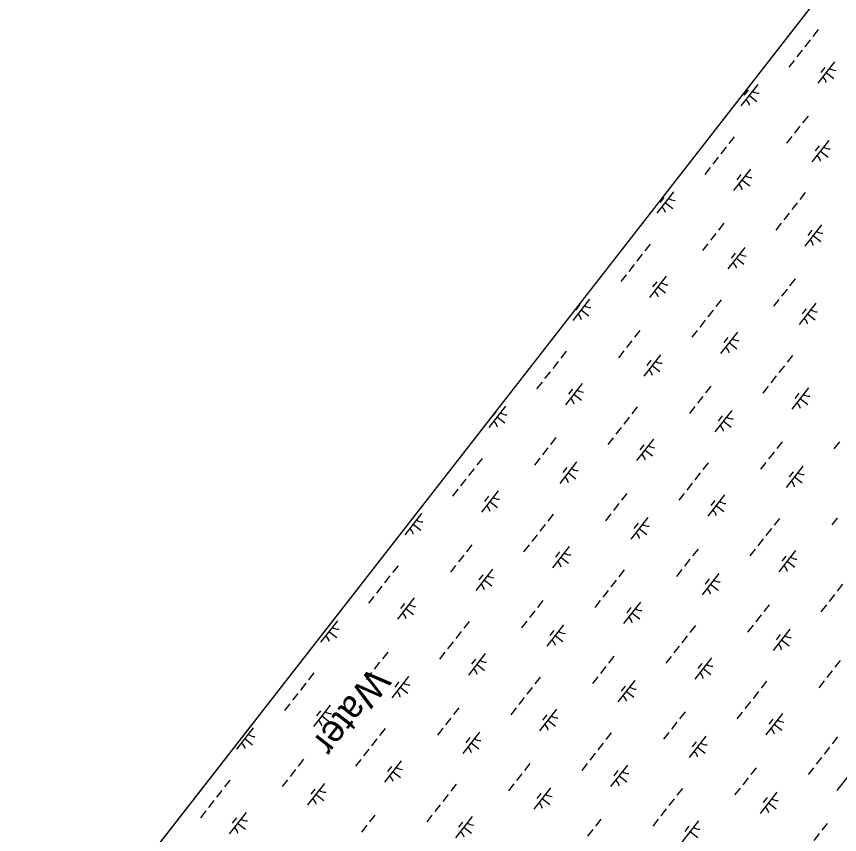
# Model space of a CAD drawing. Extents: x 3896831 to 3918110, y 171006 to 193349.
# Drawn here: x 3901021 to 3902537, y 179403 to 180910 of the extents above; entities that cross this region are included whole.
import ezdxf

# ---------------------------------------------------------------- set-up
doc = ezdxf.new("R2010")
doc.units = 0
for name, color, linetype in [('V-GRID-FRAM', 7, 'Continuous'), ('V-RIVR-IDEN', 7, 'Continuous'), ('V-WETL-SWMP', 7, 'Continuous')]:
    doc.layers.add(name, color=color, linetype=linetype)

msp = doc.modelspace()

# ---------------------------------------------------------------- linework, layer by layer
at = {"layer": 'V-GRID-FRAM'}
msp.add_lwpolyline([(3916044.9, 184610), (3906752.8, 172754.1), (3900055.1, 177809.8), (3909313.3, 189695.8), (3916044.9, 184610)], dxfattribs=at)
at = {"layer": 'V-WETL-SWMP'}
for p, q in [((3902531.9, 180989.7), (3901227.8, 179315.5)), ((3902497.5, 180886.2), (3902487.7, 180873.6)), ((3902482.7, 180867.3), (3902472.9, 180854.7)), ((3902467.9, 180848.4), (3902458.1, 180835.8)), ((3902453.1, 180829.5), (3902443.3, 180816.9)), ((3902527.3, 180826.8), (3902496.4, 180787.4)), ((3902509.5, 180816.6), (3902502.1, 180807.1)), ((3902511.8, 180807.1), (3902526, 180796)), ((3902385.9, 180784.8), (3902355, 180745.5)), ((3902368.1, 180774.6), (3902360.7, 180765.2)), ((3902370.4, 180765.2), (3902384.6, 180754)), ((3902478.6, 180727), (3902468.7, 180714.4)), ((3902463.8, 180708.1), (3902453.9, 180695.6)), ((3902342.7, 180688.7), (3902332.9, 180676.1)), ((3902449, 180689.3), (3902439.1, 180676.7)), ((3902516.8, 180682.2), (3902485.9, 180642.9)), ((3902499, 180672), (3902491.6, 180662.6)), ((3902327.9, 180669.8), (3902318.1, 180657.2)), ((3902501.4, 180662.5), (3902515.5, 180651.4)), ((3902313.1, 180650.9), (3902303.3, 180638.3)), ((3902298.3, 180632), (3902288.4, 180619.4)), ((3902372.4, 180629.3), (3902341.6, 180589.9)), ((3902354.7, 180619.1), (3902347.3, 180609.6)), ((3902357, 180609.6), (3902371.2, 180598.5)), ((3902231.1, 180587.3), (3902200.2, 180548)), ((3902473.6, 180586.1), (3902463.8, 180573.5)), ((3902213.3, 180577.1), (3902205.9, 180567.7)), ((3902215.6, 180567.6), (3902229.8, 180556.5)), ((3902458.8, 180567.2), (3902449, 180554.6)), ((3902444, 180548.3), (3902434.2, 180535.7)), ((3902323.8, 180529.5), (3902313.9, 180516.9)), ((3902429.2, 180529.4), (3902419.4, 180516.8)), ((3902503.4, 180526.6), (3902472.5, 180487.3)), ((3902309, 180510.6), (3902299.1, 180498)), ((3902485.6, 180516.5), (3902478.2, 180507)), ((3902487.9, 180507), (3902502.1, 180495.9)), ((3902187.9, 180491.1), (3902178.1, 180478.6)), ((3902294.2, 180491.7), (3902284.3, 180479.1)), ((3902362, 180484.7), (3902331.1, 180445.3)), ((3902344.2, 180474.5), (3902336.8, 180465.1)), ((3902173.1, 180472.3), (3902163.2, 180459.7)), ((3902346.6, 180465), (3902360.7, 180453.9)), ((3902158.3, 180453.4), (3902148.4, 180440.8)), ((3902143.5, 180434.5), (3902133.6, 180421.9)), ((3902217.6, 180431.7), (3902186.8, 180392.4)), ((3902199.9, 180421.5), (3902192.4, 180412.1)), ((3902454.7, 180426.9), (3902444.8, 180414.3)), ((3902202.2, 180412.1), (3902216.4, 180401)), ((3902439.9, 180408), (3902430, 180395.4)), ((3902076.3, 180389.8), (3902045.4, 180350.4)), ((3902318.8, 180388.5), (3902309, 180375.9)), ((3902425.1, 180389.1), (3902415.2, 180376.5)), ((3902492.9, 180382.1), (3902462.1, 180342.7)), ((3902058.5, 180379.6), (3902051.1, 180370.2)), ((3902060.8, 180370.1), (3902075, 180359)), ((3902304, 180369.6), (3902294.2, 180357.1)), ((3902475.1, 180371.9), (3902467.7, 180362.5)), ((3902477.5, 180362.4), (3902491.6, 180351.3)), ((3902289.2, 180350.8), (3902279.4, 180338.2)), ((3902169, 180332), (3902159.1, 180319.4)), ((3902274.4, 180331.9), (3902264.6, 180319.3)), ((3902348.6, 180329.1), (3902317.7, 180289.8)), ((3902154.2, 180313.1), (3902144.3, 180300.5)), ((3902330.8, 180318.9), (3902323.4, 180309.5)), ((3902333.1, 180309.5), (3902347.3, 180298.4)), ((3902033.1, 180293.6), (3902023.2, 180281)), ((3902139.4, 180294.2), (3902129.5, 180281.6)), ((3902207.2, 180287.2), (3902176.3, 180247.8)), ((3902189.4, 180277), (3902182, 180267.5)), ((3902449.8, 180285.9), (3902439.9, 180273.3)), ((3902018.3, 180274.7), (3902008.4, 180262.1)), ((3902191.8, 180267.5), (3902205.9, 180256.4)), ((3902435, 180267), (3902425.1, 180254.4)), ((3902003.5, 180255.8), (3901993.6, 180243.3)), ((3902420.2, 180248.1), (3902410.3, 180235.6)), ((3901988.7, 180237), (3901978.8, 180224.4)), ((3902062.8, 180234.2), (3902032, 180194.9)), ((3902045, 180224), (3902037.6, 180214.6)), ((3902299.9, 180229.4), (3902290, 180216.8)), ((3902405.3, 180229.3), (3902395.5, 180216.7)), ((3902479.5, 180226.5), (3902448.6, 180187.2)), ((3902461.7, 180216.3), (3902454.3, 180206.9)), ((3902047.4, 180214.5), (3902061.6, 180203.4)), ((3902285.1, 180210.5), (3902275.2, 180197.9)), ((3902464.1, 180206.8), (3902478.2, 180195.7)), ((3901921.4, 180192.3), (3901890.6, 180152.9)), ((3902164, 180191), (3902154.2, 180178.4)), ((3902270.3, 180191.6), (3902260.4, 180179)), ((3901903.7, 180182.1), (3901896.3, 180172.6)), ((3901906, 180172.6), (3901920.2, 180161.5)), ((3902149.2, 180172.1), (3902139.4, 180159.5)), ((3902338.1, 180184.6), (3902307.2, 180145.2)), ((3902320.3, 180174.4), (3902312.9, 180164.9)), ((3902322.7, 180164.9), (3902336.8, 180153.8)), ((3902134.4, 180153.2), (3902124.6, 180140.6)), ((3902014.2, 180134.5), (3902004.3, 180121.9)), ((3902119.6, 180134.4), (3902109.8, 180121.8)), ((3902193.8, 180131.6), (3902162.9, 180092.3)), ((3902430.8, 180126.8), (3902420.9, 180114.2)), ((3902536.3, 180126.7), (3902526.4, 180114.1)), ((3901999.4, 180115.6), (3901989.5, 180103)), ((3902176, 180121.4), (3902168.6, 180112)), ((3902178.3, 180111.9), (3902192.5, 180100.8)), ((3901878.3, 180096.1), (3901868.4, 180083.5)), ((3901984.5, 180096.7), (3901974.7, 180084.1)), ((3902416, 180107.9), (3902406.1, 180095.3)), ((3902052.4, 180089.7), (3902021.5, 180050.3)), ((3902034.6, 180079.5), (3902027.2, 180070)), ((3902295, 180088.4), (3902285.1, 180075.8)), ((3902401.2, 180089), (3902391.3, 180076.4)), ((3902469, 180082), (3902438.2, 180042.6)), ((3901863.5, 180077.2), (3901853.6, 180064.6)), ((3902036.9, 180070), (3902051.1, 180058.9)), ((3902280.2, 180069.5), (3902270.3, 180056.9)), ((3902451.2, 180071.8), (3902443.8, 180062.3)), ((3901848.7, 180058.3), (3901838.8, 180045.7)), ((3902265.3, 180050.6), (3902255.5, 180038)), ((3902453.6, 180062.3), (3902467.8, 180051.2)), ((3901833.9, 180039.4), (3901824, 180026.8)), ((3901908, 180036.7), (3901877.2, 179997.4)), ((3901890.2, 180026.5), (3901882.8, 180017.1)), ((3902145.1, 180031.9), (3902135.2, 180019.3)), ((3902250.5, 180031.7), (3902240.7, 180019.1)), ((3902324.7, 180029), (3902293.8, 179989.7)), ((3902306.9, 180018.8), (3902299.5, 180009.4)), ((3901892.6, 180017), (3901906.8, 180005.9)), ((3902130.3, 180013), (3902120.4, 180000.4)), ((3902309.3, 180009.3), (3902323.4, 179998.2)), ((3901766.6, 179994.8), (3901735.8, 179955.4)), ((3902009.2, 179993.5), (3901999.4, 179980.9)), ((3902115.5, 179994.1), (3902105.6, 179981.5)), ((3901751.2, 179975.1), (3901765.4, 179964)), ((3901994.4, 179974.6), (3901984.6, 179962)), ((3902183.3, 179987.1), (3902152.4, 179947.7)), ((3902165.5, 179976.9), (3902158.1, 179967.4)), ((3902425.9, 179985.8), (3902416, 179973.2)), ((3902532.1, 179986.4), (3902522.2, 179973.8)), ((3902167.9, 179967.4), (3902182, 179956.3)), ((3902411.1, 179966.9), (3902401.2, 179954.3)), ((3901979.6, 179955.7), (3901969.8, 179943.1)), ((3902396.3, 179948), (3902386.4, 179935.4)), ((3901859.4, 179937), (3901849.5, 179924.4)), ((3901964.8, 179936.8), (3901954.9, 179924.2)), ((3902039, 179934.1), (3902008.1, 179894.7)), ((3902276, 179929.3), (3902266.1, 179916.7)), ((3902381.5, 179929.1), (3902371.6, 179916.5)), ((3901844.5, 179918.1), (3901834.7, 179905.5)), ((3902021.2, 179923.9), (3902013.8, 179914.5)), ((3902023.5, 179914.4), (3902037.7, 179903.3)), ((3902455.6, 179926.4), (3902424.7, 179887)), ((3902437.8, 179916.2), (3902430.4, 179906.8)), ((3901723.5, 179898.6), (3901713.6, 179886)), ((3901829.7, 179899.2), (3901819.9, 179886.6)), ((3902261.2, 179910.4), (3902251.3, 179897.8)), ((3902440.2, 179906.7), (3902454.3, 179895.6)), ((3901897.6, 179892.1), (3901866.7, 179852.8)), ((3901879.8, 179882), (3901872.4, 179872.5)), ((3902140.1, 179890.9), (3902130.3, 179878.3)), ((3902246.4, 179891.5), (3902236.5, 179878.9)), ((3902314.2, 179884.4), (3902283.4, 179845.1)), ((3901708.7, 179879.7), (3901698.8, 179867.1)), ((3901882.1, 179872.5), (3901896.3, 179861.4)), ((3902125.3, 179872), (3902115.5, 179859.4)), ((3902296.4, 179874.3), (3902289, 179864.8)), ((3901693.9, 179860.8), (3901684, 179848.2)), ((3902110.5, 179853.1), (3902100.7, 179840.5)), ((3902298.8, 179864.8), (3902312.9, 179853.7)), ((3902542, 179864.3), (3902532.1, 179851.7)), ((3901679.1, 179841.9), (3901669.2, 179829.3)), ((3901753.2, 179839.2), (3901722.4, 179799.8)), ((3902527.2, 179845.4), (3902517.3, 179832.8)), ((3901735.4, 179829), (3901728, 179819.6)), ((3901990.3, 179834.4), (3901980.4, 179821.8)), ((3902095.7, 179834.2), (3902085.9, 179821.6)), ((3902169.9, 179831.5), (3902139, 179792.1)), ((3902152.1, 179821.3), (3902144.7, 179811.9)), ((3902406.9, 179826.7), (3902397, 179814.1)), ((3902512.4, 179826.5), (3902502.5, 179813.9)), ((3901737.8, 179819.5), (3901752, 179808.4)), ((3901975.5, 179815.5), (3901965.6, 179802.9)), ((3902154.4, 179811.8), (3902168.6, 179800.7)), ((3902392.1, 179807.8), (3902382.2, 179795.2)), ((3901611.8, 179797.2), (3901581, 179757.9)), ((3901854.4, 179796), (3901844.6, 179783.4)), ((3901960.7, 179796.6), (3901950.8, 179784)), ((3901596.4, 179777.6), (3901610.6, 179766.5)), ((3901839.6, 179777.1), (3901829.8, 179764.5)), ((3902028.5, 179789.5), (3901997.6, 179750.2)), ((3902010.7, 179779.3), (3902003.3, 179769.9)), ((3902271.1, 179788.3), (3902261.2, 179775.7)), ((3902377.3, 179788.9), (3902367.4, 179776.3)), ((3902445.1, 179781.8), (3902414.3, 179742.5)), ((3902013.1, 179769.9), (3902027.2, 179758.8)), ((3902256.3, 179769.4), (3902246.4, 179756.8)), ((3902427.3, 179771.6), (3902419.9, 179762.2)), ((3902429.7, 179762.2), (3902443.9, 179751.1)), ((3901824.8, 179758.2), (3901814.9, 179745.6)), ((3902241.5, 179750.5), (3902231.6, 179737.9)), ((3901704.5, 179739.4), (3901694.7, 179726.9)), ((3901810, 179739.3), (3901800.1, 179726.7)), ((3901884.1, 179736.6), (3901853.3, 179697.2)), ((3902121.2, 179731.7), (3902111.3, 179719.2)), ((3902226.7, 179731.6), (3902216.8, 179719)), ((3901689.7, 179720.6), (3901679.9, 179708)), ((3901866.4, 179726.4), (3901858.9, 179716.9)), ((3901868.7, 179716.9), (3901882.9, 179705.8)), ((3902300.8, 179728.9), (3902269.9, 179689.5)), ((3902283, 179718.7), (3902275.6, 179709.2)), ((3902537.8, 179724), (3902528, 179711.5)), ((3901568.7, 179701.1), (3901558.8, 179688.5)), ((3901674.9, 179701.7), (3901665.1, 179689.1)), ((3902106.4, 179712.9), (3902096.5, 179700.3)), ((3902285.4, 179709.2), (3902299.5, 179698.1)), ((3902523, 179705.2), (3902513.2, 179692.6)), ((3901742.8, 179694.6), (3901711.9, 179655.3)), ((3901985.3, 179693.4), (3901975.5, 179680.8)), ((3902091.6, 179694), (3902081.7, 179681.4)), ((3902159.4, 179686.9), (3902128.6, 179647.6)), ((3902402, 179685.7), (3902392.1, 179673.1)), ((3902508.2, 179686.3), (3902498.4, 179673.7)), ((3901553.9, 179682.2), (3901544, 179669.6)), ((3901725, 179684.4), (3901717.6, 179675)), ((3901727.3, 179675), (3901741.5, 179663.9)), ((3901970.5, 179674.5), (3901960.7, 179661.9)), ((3902141.6, 179676.7), (3902134.2, 179667.3)), ((3901539.1, 179663.3), (3901529.2, 179650.7)), ((3901955.7, 179655.6), (3901945.9, 179643)), ((3902144, 179667.3), (3902158.1, 179656.2)), ((3902387.2, 179666.8), (3902377.3, 179654.2)), ((3901524.3, 179644.4), (3901514.4, 179631.8)), ((3901598.4, 179641.7), (3901567.6, 179602.3)), ((3902372.4, 179647.9), (3902362.5, 179635.3)), ((3901580.6, 179631.5), (3901573.2, 179622)), ((3901835.5, 179636.8), (3901825.6, 179624.2)), ((3901940.9, 179636.7), (3901931.1, 179624.1)), ((3902015.1, 179634), (3901984.2, 179594.6)), ((3902252.1, 179629.1), (3902242.2, 179616.5)), ((3902357.6, 179629), (3902347.7, 179616.4)), ((3902431.7, 179626.3), (3902400.9, 179586.9)), ((3901583, 179622), (3901597.2, 179610.9)), ((3901820.7, 179617.9), (3901810.8, 179605.4)), ((3901997.3, 179623.8), (3901989.9, 179614.3)), ((3901999.6, 179614.3), (3902013.8, 179603.2)), ((3902237.3, 179610.2), (3902227.4, 179597.7)), ((3902413.9, 179616.1), (3902406.5, 179606.6)), ((3901457, 179599.7), (3901426.2, 179560.4)), ((3901699.6, 179598.5), (3901689.7, 179585.9)), ((3901805.9, 179599.1), (3901796, 179586.5)), ((3902416.3, 179606.6), (3902430.5, 179595.5)), ((3901441.6, 179580), (3901455.8, 179568.9)), ((3901684.8, 179579.6), (3901674.9, 179567)), ((3901873.7, 179592), (3901842.8, 179552.7)), ((3901855.9, 179581.8), (3901848.5, 179572.4)), ((3902116.3, 179590.8), (3902106.4, 179578.2)), ((3902222.5, 179591.4), (3902212.6, 179578.8)), ((3902290.3, 179584.3), (3902259.5, 179545)), ((3902532.9, 179583.1), (3902523, 179570.5)), ((3901858.3, 179572.3), (3901872.4, 179561.2)), ((3902101.5, 179571.9), (3902091.6, 179559.3)), ((3902272.5, 179574.1), (3902265.1, 179564.7)), ((3902274.9, 179564.6), (3902289.1, 179553.5)), ((3902518.1, 179564.2), (3902508.2, 179551.6)), ((3901670, 179560.7), (3901660.1, 179548.1)), ((3902086.7, 179553), (3902076.8, 179540.4)), ((3901549.7, 179541.9), (3901539.9, 179529.3)), ((3901655.2, 179541.8), (3901645.3, 179529.2)), ((3901729.3, 179539.1), (3901698.5, 179499.7)), ((3901966.4, 179534.2), (3901956.5, 179521.6)), ((3902071.8, 179534.1), (3902062, 179521.5)), ((3902503.3, 179545.3), (3902493.4, 179532.7)), ((3901534.9, 179523), (3901525.1, 179510.4)), ((3901711.5, 179528.9), (3901704.1, 179519.4)), ((3901713.9, 179519.4), (3901728.1, 179508.3)), ((3902146, 179531.4), (3902115.1, 179492)), ((3902128.2, 179521.2), (3902120.8, 179511.7)), ((3902383, 179526.5), (3902373.2, 179513.9)), ((3902488.5, 179526.4), (3902478.6, 179513.8)), ((3902562.6, 179523.7), (3902531.8, 179484.3)), ((3901413.9, 179503.6), (3901404, 179491)), ((3901520.1, 179504.2), (3901510.3, 179491.6)), ((3901951.6, 179515.3), (3901941.7, 179502.7)), ((3902130.6, 179511.7), (3902144.7, 179500.6)), ((3902368.2, 179507.6), (3902358.4, 179495)), ((3901587.9, 179497.1), (3901557.1, 179457.8)), ((3901830.5, 179495.9), (3901820.7, 179483.3)), ((3901936.8, 179496.5), (3901926.9, 179483.9)), ((3902004.6, 179489.4), (3901973.7, 179450.1)), ((3902247.2, 179488.2), (3902237.3, 179475.6)), ((3902353.4, 179488.8), (3902343.5, 179476.2)), ((3901399.1, 179484.7), (3901389.2, 179472.1)), ((3901570.2, 179486.9), (3901562.8, 179477.5)), ((3901572.5, 179477.4), (3901586.7, 179466.3)), ((3901815.7, 179477), (3901805.9, 179464.4)), ((3901986.8, 179479.2), (3901979.4, 179469.8)), ((3902421.2, 179481.7), (3902390.4, 179442.4)), ((3901384.3, 179465.8), (3901374.4, 179453.2)), ((3901800.9, 179458.1), (3901791.1, 179445.5)), ((3901989.2, 179469.7), (3902003.3, 179458.6)), ((3902232.4, 179469.3), (3902222.5, 179456.7)), ((3902403.4, 179471.5), (3902396, 179462.1)), ((3902405.8, 179462), (3902420, 179450.9)), ((3901369.5, 179446.9), (3901359.6, 179434.3)), ((3901443.6, 179444.2), (3901412.8, 179404.8)), ((3902217.6, 179450.4), (3902207.7, 179437.8)), ((3901425.8, 179434), (3901418.4, 179424.5)), ((3901680.7, 179439.3), (3901670.8, 179426.7)), ((3901786.1, 179439.2), (3901776.3, 179426.6)), ((3901860.3, 179436.5), (3901829.4, 179397.1)), ((3902097.3, 179431.6), (3902087.4, 179419)), ((3902202.8, 179431.5), (3902192.9, 179418.9)), ((3902276.9, 179428.8), (3902246.1, 179389.4)), ((3901428.2, 179424.5), (3901442.4, 179413.4)), ((3901665.9, 179420.4), (3901656, 179407.8)), ((3901842.5, 179426.3), (3901835.1, 179416.8)), ((3901844.8, 179416.8), (3901859, 179405.7)), ((3902082.5, 179412.7), (3902072.6, 179400.1)), ((3902259.1, 179418.6), (3902251.7, 179409.1)), ((3902513.9, 179423.9), (3902504.1, 179411.3)), ((3902261.5, 179409.1), (3902275.6, 179398)), ((3902499.1, 179405), (3902489.3, 179392.4))]:
    msp.add_line(p, q, dxfattribs=at)
for centre, start, end in [((3902529.1, 180828.7), 231.1403, 272.6839), ((3902495, 180785.2), 11.1403, 52.6839), ((3902387.7, 180786.7), 231.1403, 272.6839), ((3902353.6, 180743.3), 11.1403, 52.6839), ((3902518.6, 180684.1), 231.1403, 272.6839), ((3902484.5, 180640.7), 11.1403, 52.6839), ((3902374.3, 180631.2), 231.1403, 272.6839), ((3902340.2, 180587.7), 11.1403, 52.6839), ((3902232.9, 180589.2), 231.1403, 272.6839), ((3902198.8, 180545.7), 11.1403, 52.6839), ((3902505.2, 180528.6), 231.1403, 272.6839), ((3902471.1, 180485.1), 11.1403, 52.6839), ((3902363.8, 180486.6), 231.1403, 272.6839), ((3902329.7, 180443.1), 11.1403, 52.6839), ((3902219.4, 180433.7), 231.1403, 272.6839), ((3902185.4, 180390.2), 11.1403, 52.6839), ((3902078.1, 180391.7), 231.1403, 272.6839), ((3902494.7, 180384), 231.1403, 272.6839), ((3902044, 180348.2), 11.1403, 52.6839), ((3902460.6, 180340.5), 11.1403, 52.6839), ((3902350.4, 180331), 231.1403, 272.6839), ((3902316.3, 180287.6), 11.1403, 52.6839), ((3902209, 180289.1), 231.1403, 272.6839), ((3902174.9, 180245.6), 11.1403, 52.6839), ((3902064.6, 180236.1), 231.1403, 272.6839), ((3902030.6, 180192.7), 11.1403, 52.6839), ((3902481.3, 180228.4), 231.1403, 272.6839), ((3902447.2, 180185), 11.1403, 52.6839), ((3901923.3, 180194.2), 231.1403, 272.6839), ((3902339.9, 180186.5), 231.1403, 272.6839), ((3901889.2, 180150.7), 11.1403, 52.6839), ((3902305.8, 180143), 11.1403, 52.6839), ((3902195.6, 180133.5), 231.1403, 272.6839), ((3902161.5, 180090.1), 11.1403, 52.6839), ((3902054.2, 180091.6), 231.1403, 272.6839), ((3902470.8, 180083.9), 231.1403, 272.6839), ((3902020.1, 180048.1), 11.1403, 52.6839), ((3902436.7, 180040.4), 11.1403, 52.6839), ((3901909.8, 180038.6), 231.1403, 272.6839), ((3901875.8, 179995.1), 11.1403, 52.6839), ((3902326.5, 180030.9), 231.1403, 272.6839), ((3902292.4, 179987.4), 11.1403, 52.6839), ((3901768.4, 179996.7), 231.1403, 272.6839), ((3902185.1, 179989), 231.1403, 272.6839), ((3901734.4, 179953.2), 11.1403, 52.6839), ((3902151, 179945.5), 11.1403, 52.6839), ((3902040.8, 179936), 231.1403, 272.6839), ((3902457.4, 179928.3), 231.1403, 272.6839), ((3902006.7, 179892.5), 11.1403, 52.6839), ((3902423.3, 179884.8), 11.1403, 52.6839), ((3901899.4, 179894.1), 231.1403, 272.6839), ((3902316, 179886.4), 231.1403, 272.6839), ((3901865.3, 179850.6), 11.1403, 52.6839), ((3902281.9, 179842.9), 11.1403, 52.6839), ((3901755, 179841.1), 231.1403, 272.6839), ((3901721, 179797.6), 11.1403, 52.6839), ((3902171.7, 179833.4), 231.1403, 272.6839), ((3902137.6, 179789.9), 11.1403, 52.6839), ((3901613.6, 179799.2), 231.1403, 272.6839), ((3902030.3, 179791.5), 231.1403, 272.6839), ((3901579.6, 179755.7), 11.1403, 52.6839), ((3901996.2, 179748), 11.1403, 52.6839), ((3902446.9, 179783.8), 231.1403, 272.6839), ((3902412.8, 179740.3), 11.1403, 52.6839), ((3901885.9, 179738.5), 231.1403, 272.6839), ((3902302.6, 179730.8), 231.1403, 272.6839), ((3901851.9, 179695), 11.1403, 52.6839), ((3902268.5, 179687.3), 11.1403, 52.6839), ((3901744.6, 179696.5), 231.1403, 272.6839), ((3902161.2, 179688.8), 231.1403, 272.6839), ((3901710.5, 179653.1), 11.1403, 52.6839), ((3902127.1, 179645.4), 11.1403, 52.6839), ((3901600.2, 179643.6), 231.1403, 272.6839), ((3901566.1, 179600.1), 11.1403, 52.6839), ((3902016.9, 179635.9), 231.1403, 272.6839), ((3902433.5, 179628.2), 231.1403, 272.6839), ((3901982.8, 179592.4), 11.1403, 52.6839), ((3902399.4, 179584.7), 11.1403, 52.6839), ((3901458.8, 179601.6), 231.1403, 272.6839), ((3901875.5, 179593.9), 231.1403, 272.6839), ((3901424.8, 179558.2), 11.1403, 52.6839), ((3901841.4, 179550.5), 11.1403, 52.6839), ((3902292.1, 179586.2), 231.1403, 272.6839), ((3902258, 179542.8), 11.1403, 52.6839), ((3901731.1, 179541), 231.1403, 272.6839), ((3902147.8, 179533.3), 231.1403, 272.6839), ((3901697.1, 179497.5), 11.1403, 52.6839), ((3902113.7, 179489.8), 11.1403, 52.6839), ((3901589.8, 179499), 231.1403, 272.6839), ((3902006.4, 179491.3), 231.1403, 272.6839), ((3901555.7, 179455.6), 11.1403, 52.6839), ((3901972.3, 179447.9), 11.1403, 52.6839), ((3902423, 179483.6), 231.1403, 272.6839), ((3902389, 179440.2), 11.1403, 52.6839), ((3901445.4, 179446.1), 231.1403, 272.6839), ((3901411.3, 179402.6), 11.1403, 52.6839), ((3901862.1, 179438.4), 231.1403, 272.6839), ((3902278.7, 179430.7), 231.1403, 272.6839), ((3901828, 179394.9), 11.1403, 52.6839)]:
    msp.add_arc(centre, 17.6, start, end, dxfattribs=at)

# ---------------------------------------------------------------- texts
at = {"layer": 'V-RIVR-IDEN'}
msp.add_text('Water', height=50, rotation=232.0843, dxfattribs=at).set_placement((3901673.5, 179714.1))

doc.saveas('drawing.dxf')
